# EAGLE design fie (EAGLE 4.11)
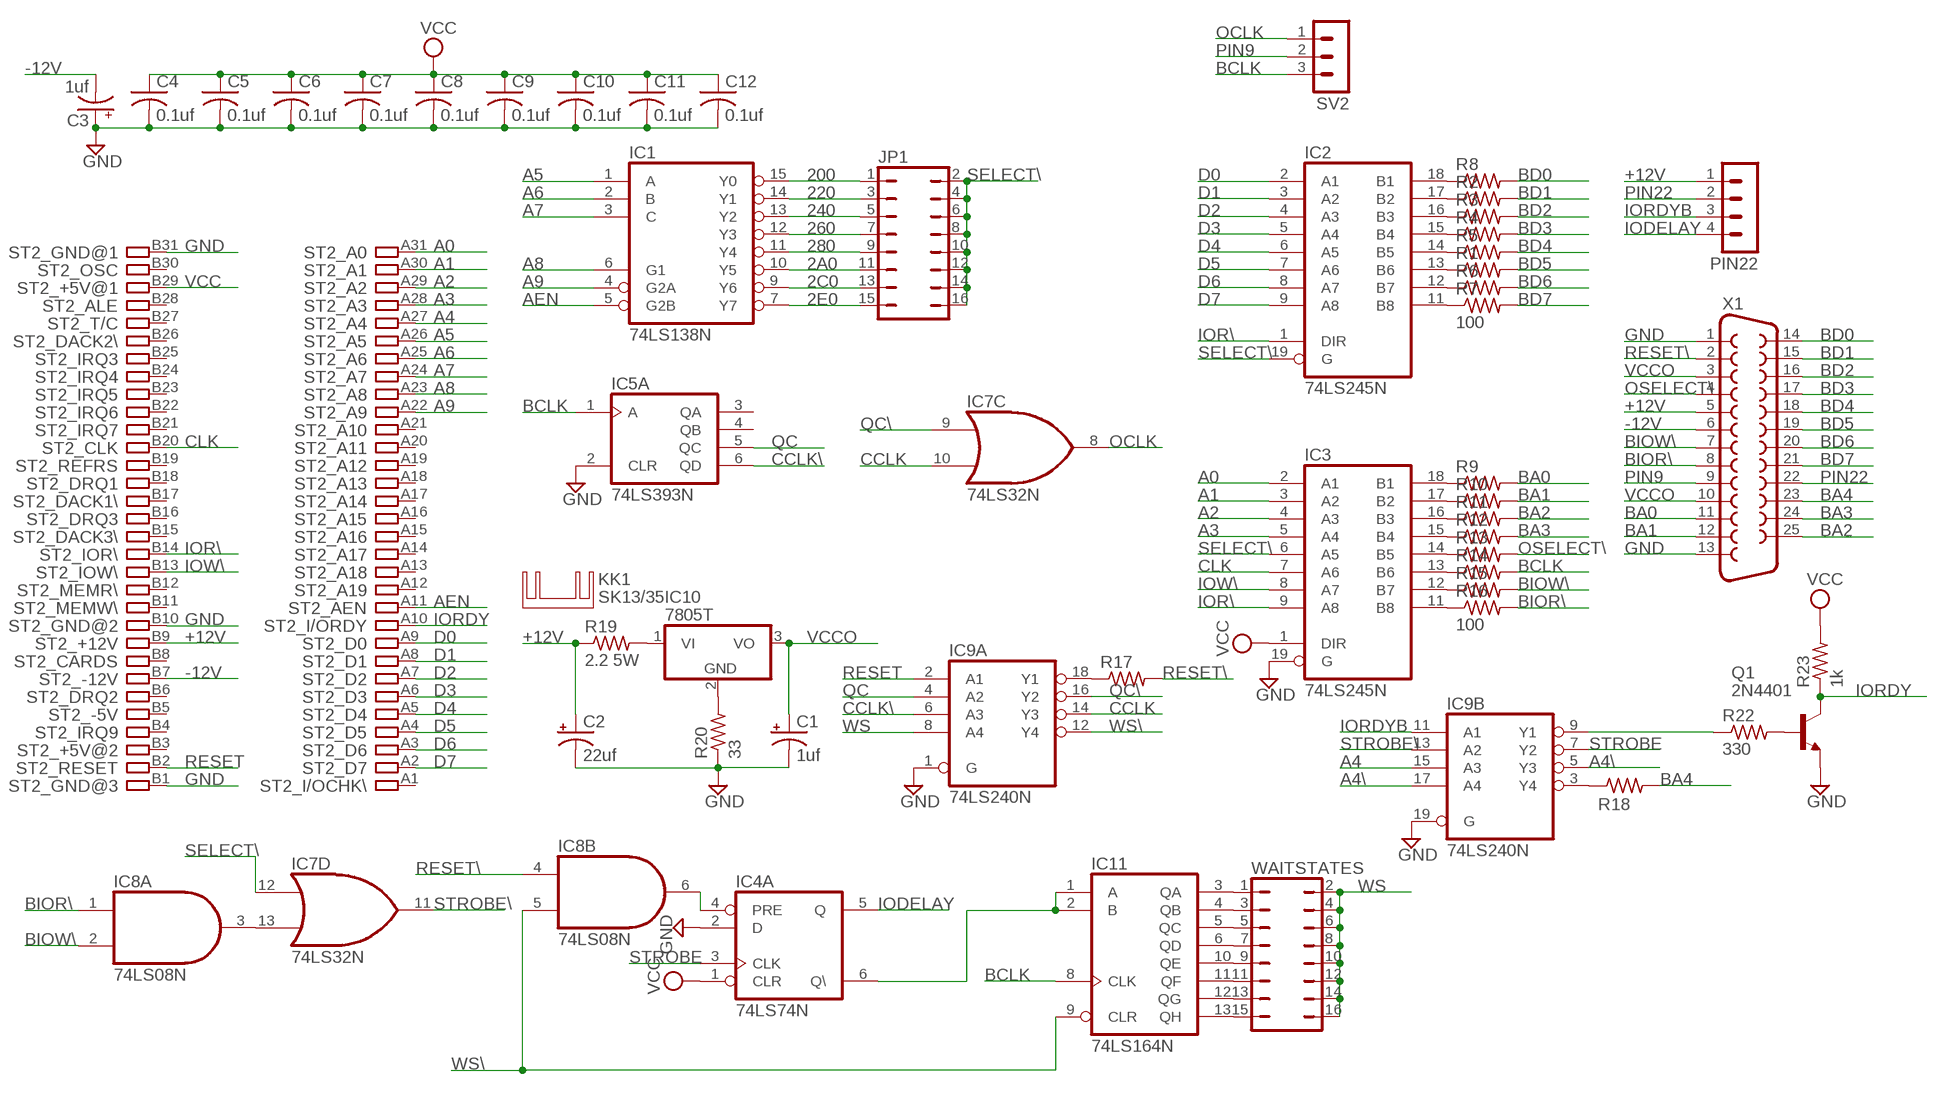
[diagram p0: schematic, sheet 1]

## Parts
C1  1uf  CPOL-USE5-10.5  [E5-10,5]
C2  22uf  CPOL-USE5-10.5  [E5-10,5]
C3  1uf  CPOL-USE5-10.5  [E5-10,5]
C4  0.1uf  C-US050-025X075  [C050-025X075]
C5  0.1uf  C-US050-025X075  [C050-025X075]
C6  0.1uf  C-US050-025X075  [C050-025X075]
C7  0.1uf  C-US050-025X075  [C050-025X075]
C8  0.1uf  C-US050-025X075  [C050-025X075]
C9  0.1uf  C-US050-025X075  [C050-025X075]
C10  0.1uf  C-US050-025X075  [C050-025X075]
C11  0.1uf  C-US050-025X075  [C050-025X075]
C12  0.1uf  C-US050-025X075  [C050-025X075]
IC1  74LS138N  [DIL16]
IC2  74LS245N  [DIL20]
IC3  74LS245N  [DIL20]
IC4  74LS74N  [DIL14]
IC5  74LS393N  [DIL14]
IC7  74LS32N  [DIL14]
IC8  74LS08N  [DIL14]
IC9  74LS240N  [DIL20]
IC10  7805T  [TO220H]
IC11  74LS164N  [DIL14]
JP1  JP8Q  [JP8Q]
KK1  SK13/35  [SK13/35]
PIN22  MA04-1  [MA04-1]
Q1  2N4401  2N4416  [TO92]
R1  R-US_0207/10  [0207/10]
R2  R-US_0207/10  [0207/10]
R3  R-US_0207/10  [0207/10]
R4  R-US_0207/10  [0207/10]
R5  R-US_0207/10  [0207/10]
R6  R-US_0207/10  [0207/10]
R7  100  R-US_0207/10  [0207/10]
R8  R-US_0207/10  [0207/10]
R9  R-US_0207/10  [0207/10]
R10  R-US_0207/10  [0207/10]
R11  R-US_0207/10  [0207/10]
R12  R-US_0207/10  [0207/10]
R13  R-US_0207/10  [0207/10]
R14  R-US_0207/10  [0207/10]
R15  R-US_0207/10  [0207/10]
R16  100  R-US_0207/10  [0207/10]
R17  R-US_0207/10  [0207/10]
R18  R-US_0207/10  [0207/10]
R19  2.2 5W  R-US_0922/22  [0922/22]
R20  33  R-US_0207/10  [0207/10]
R22  330  R-US_0207/10  [0207/10]
R23  1k  R-US_0207/10  [0207/10]
ST2  IBM8BIT  [IBM8BIT]
SV2  MA03-1  [MA03-1]
WAITSTATES  JP8Q  [JP8Q]
X1  F25H  [F25H]

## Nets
2A0: IC1.10(Y5) JP1.11
2C0: IC1.9(Y6) JP1.13
2E0: IC1.7(Y7) JP1.15
200: IC1.15(Y0) JP1.1
220: IC1.14(Y1) JP1.3
240: IC1.13(Y2) JP1.5
260: IC1.12(Y3) JP1.7
280: IC1.11(Y4) JP1.9
+12V [Power]: C2.+ PIN22.1 R19.1 ST2.B9 X1.5
-12V [Power]: C3.- ST2.B7 X1.6
A0: IC3.2(A1) ST2.A31
A1: IC3.3(A2) ST2.A30
A2: IC3.4(A3) ST2.A29
A3: IC3.5(A4) ST2.A28
A4: IC9.15(B:A3) ST2.A27
A4\: IC9.5(B:Y3) IC9.17(B:A4)
A5: IC1.1(A) ST2.A26
A6: IC1.2(B) ST2.A25
A7: IC1.3(C) ST2.A24
A8: IC1.6(G1) ST2.A23
A9: IC1.4(G2A) ST2.A22
AEN: IC1.5(G2B) ST2.A11
BA0: R9.2 X1.11
BA1: R10.2 X1.12
BA2: R11.2 X1.25
BA3: R12.2 X1.24
BA4: R18.2 X1.23
BCLK: IC5.1(A:A) IC11.8(CLK) R14.2 SV2.3
BD0: R8.2 X1.14
BD1: R2.2 X1.15
BD2: R3.2 X1.16
BD3: R4.2 X1.17
BD4: R5.2 X1.18
BD5: R1.2 X1.19
BD6: R6.2 X1.20
BD7: R7.2 X1.21
BIOR\: IC8.1(A:I0) R16.2 X1.8
BIOW\: IC8.2(A:I1) R15.2 X1.7
CCLK: IC7.10(C:I1) IC9.14(A:Y3)
CCLK\: IC5.6(A:QD) IC9.6(A:A3)
CLK: IC3.7(A6) ST2.B20
D0: IC2.2(A1) ST2.A9
D1: IC2.3(A2) ST2.A8
D2: IC2.4(A3) ST2.A7
D3: IC2.5(A4) ST2.A6
D4: IC2.6(A5) ST2.A5
D5: IC2.7(A6) ST2.A4
D6: IC2.8(A7) ST2.A3
D7: IC2.9(A8) ST2.A2
GND [Power]: C1.- C2.- C3.+ C4.2 C5.2 C6.2 C7.2 C8.2 C9.2 C10.2 C11.2 C12.2 IC3.19(G) IC4.2(A:D) IC5.2(A:CLR) IC9.1(A:G) IC9.19(B:G) Q1.3(E) R20.1 ST2.B1 ST2.B10 ST2.B31 X1.1 X1.13
IODELAY: IC4.5(A:Q) PIN22.4
IOR\: IC2.1(DIR) IC3.9(A8) ST2.B14
IORDY: Q1.1(C) R23.1 ST2.A10
IORDYB: IC9.11(B:A1) PIN22.3
IOW\: IC3.8(A7) ST2.B13
N$2 [Power]: IC10.2(GND) R20.2
N$3: IC2.13(B6) R1.1
N$4: IC2.17(B2) R2.1
N$5: IC2.16(B3) R3.1
N$6: IC2.15(B4) R4.1
N$7: IC2.14(B5) R5.1
N$8: IC2.12(B7) R6.1
N$9: IC2.11(B8) R7.1
N$10: IC2.18(B1) R8.1
N$11: IC3.18(B1) R9.1
N$12: IC3.17(B2) R10.1
N$13: IC3.16(B3) R11.1
N$14: IC3.15(B4) R12.1
N$15: IC3.14(B5) R13.1
N$16: IC3.13(B6) R14.1
N$17: IC3.12(B7) R15.1
N$18: IC3.11(B8) R16.1
N$19: IC9.18(A:Y1) R17.1
N$20: IC11.3(QA) WAITSTATES.1
N$21: IC11.4(QB) WAITSTATES.3
N$23: IC9.3(B:Y4) R18.1
N$25 [Power]: IC10.1(VI) R19.2
N$27: IC11.5(QC) WAITSTATES.5
N$28: IC11.6(QD) WAITSTATES.7
N$29: IC7.13(D:I1) IC8.3(A:O)
N$30: IC4.4(A:PRE) IC8.6(B:O)
N$31: IC11.10(QE) WAITSTATES.9
N$32: IC9.9(B:Y1) R22.1
N$34: IC11.11(QF) WAITSTATES.11
N$35: IC11.12(QG) WAITSTATES.13
N$36: IC11.13(QH) WAITSTATES.15
N$37: Q1.2(B) R22.2
N$39: IC4.6(A:Q\) IC11.1(A) IC11.2(B)
OCLK: IC7.8(C:O) SV2.1
OSELECT\: R13.2 X1.4
PIN9: SV2.2 X1.9
PIN22 [Power]: PIN22.2 X1.22
QC: IC5.5(A:QC) IC9.4(A:A2)
QC\: IC7.9(C:I0) IC9.16(A:Y2)
RESET: IC9.2(A:A1) ST2.B2
RESET\: IC8.4(B:I0) R17.2 X1.2
SELECT\: IC2.19(G) IC3.6(A5) IC7.12(D:I0) JP1.2 JP1.4 JP1.6 JP1.8 JP1.10 JP1.12 JP1.14 JP1.16
STROBE: IC4.3(A:CLK) IC9.7(B:Y2)
STROBE\: IC7.11(D:O) IC9.13(B:A2)
VCC [Power]: C4.1 C5.1 C6.1 C7.1 C8.1 C9.1 C10.1 C11.1 C12.1 IC3.1(DIR) IC4.1(A:CLR) R23.2 ST2.B29
VCCO [Power]: C1.+ IC10.3(VO) X1.3 X1.10
WS: IC9.8(A:A4) WAITSTATES.2 WAITSTATES.4 WAITSTATES.6 WAITSTATES.8 WAITSTATES.10 WAITSTATES.12 WAITSTATES.14 WAITSTATES.16
WS\: IC8.5(B:I1) IC9.12(A:Y4) IC11.9(CLR)
Unconnected: IC4.8(B:Q\) IC4.9(B:Q) IC4.10(B:PRE) IC4.11(B:CLK) IC4.12(B:D) IC4.13(B:CLR) IC5.3(A:QA) IC5.4(A:QB) IC5.8(B:QD) IC5.9(B:QC) IC5.10(B:QB) IC5.11(B:QA) IC5.12(B:CLR) IC5.13(B:A) IC7.1(A:I0) IC7.2(A:I1) IC7.3(A:O) IC7.4(B:I0) IC7.5(B:I1) IC7.6(B:O) IC8.8(C:O) IC8.9(C:I0) IC8.10(C:I1) IC8.11(D:O) IC8.12(D:I0) IC8.13(D:I1) ST2.A1 ST2.A12 ST2.A13 ST2.A14 ST2.A15 ST2.A16 ST2.A17 ST2.A18 ST2.A19 ST2.A20 ST2.A21 ST2.B3 ST2.B4 ST2.B5 ST2.B6 ST2.B8 ST2.B11 ST2.B12 ST2.B15 ST2.B16 ST2.B17 ST2.B18 ST2.B19 ST2.B21 ST2.B22 ST2.B23 ST2.B24 ST2.B25 ST2.B26 ST2.B27 ST2.B28 ST2.B30

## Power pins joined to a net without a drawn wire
GND: IC1.8(GND) IC2.10(GND) IC3.10(GND) IC4.7(P:GND) IC5.7(P:GND) IC7.7(P:GND) IC8.7(P:GND) IC9.10(P:GND) IC11.7(GND)
VCC: IC1.16(VCC) IC2.20(VCC) IC3.20(VCC) IC4.14(P:VCC) IC5.14(P:VCC) IC7.14(P:VCC) IC8.14(P:VCC) IC9.20(P:VCC) IC11.14(VCC)

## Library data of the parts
C1-C3 = rcl:CPOL-US: POLARIZED CAPACITOR, American symbol
C4-C12 = rcl:C-US: CAPACITOR, American symbol
IC1 = 74xx-us:74*138: 3-line to 8-line DECODER/DEMULTIPLEXER
IC2 IC3 = 74xx-us:74*245: Octal BUS TRANSCEIVER, 3-state
IC4 = 74xx-us:74*74: Dual D type positive edge triggered FLIP FLOP, preset and clear
IC5 = 74xx-us:74*393: Dual 4-bit decade and binary COUNTER
IC7 = 74xx-us:74*32: Quad 2-input OR gate
IC8 = 74xx-us:74*08: Quad 2-input AND gate
IC9 = 74xx-us:74*240: Octal BUFFER and LINE DRIVER, 3-state
IC10 = linear:78*: Positive VOLTAGE REGULATOR
IC11 = 74xx-us:74*164: 8-bit parallel out SHIFT REGISTER
JP1 WAITSTATES = jumper:JP8Q: JUMPER
KK1 = heatsink:SK13/35: HEATSINK
PIN22 = con-lstb:MA04-1: PIN HEADER
Q1 = transistor-npn:2N4416: NPN Transistor
R1-R20 R22 R23 = rcl:R-US_: RESISTOR, American symbol
ST2 = con-pc:IBM8BIT: 8-bit CARD IBM/PC-AT
SV2 = con-lstb:MA03-1: PIN HEADER
X1 = con-subd:F25: SUB-D

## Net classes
1 Power: width 0.762 mm, drill 0.254 mm

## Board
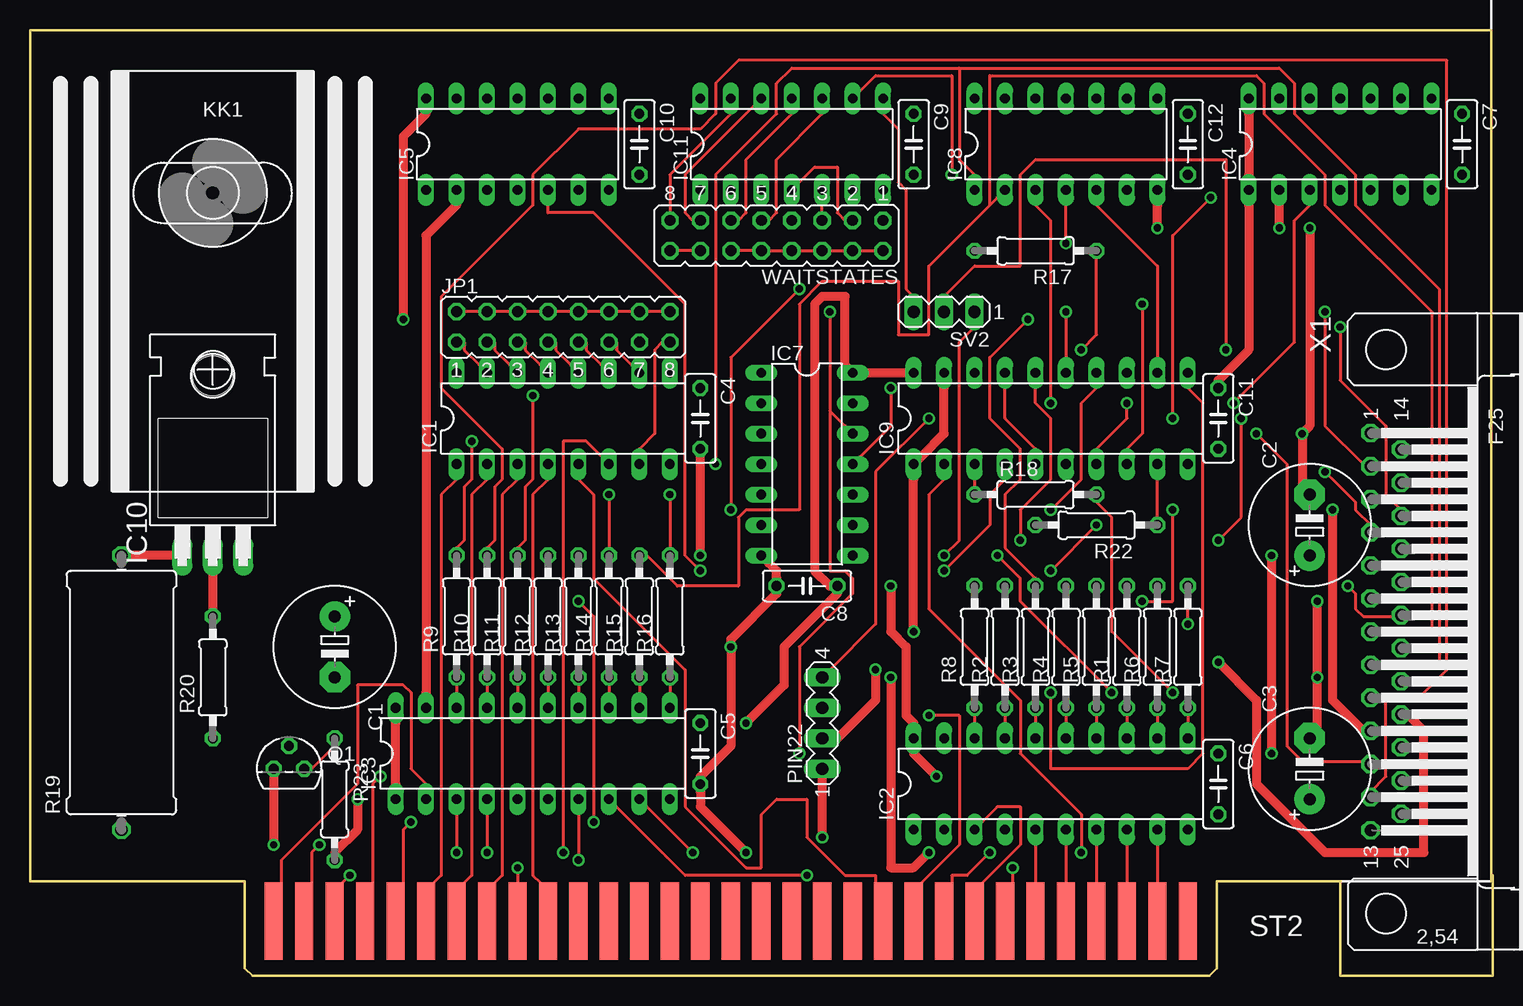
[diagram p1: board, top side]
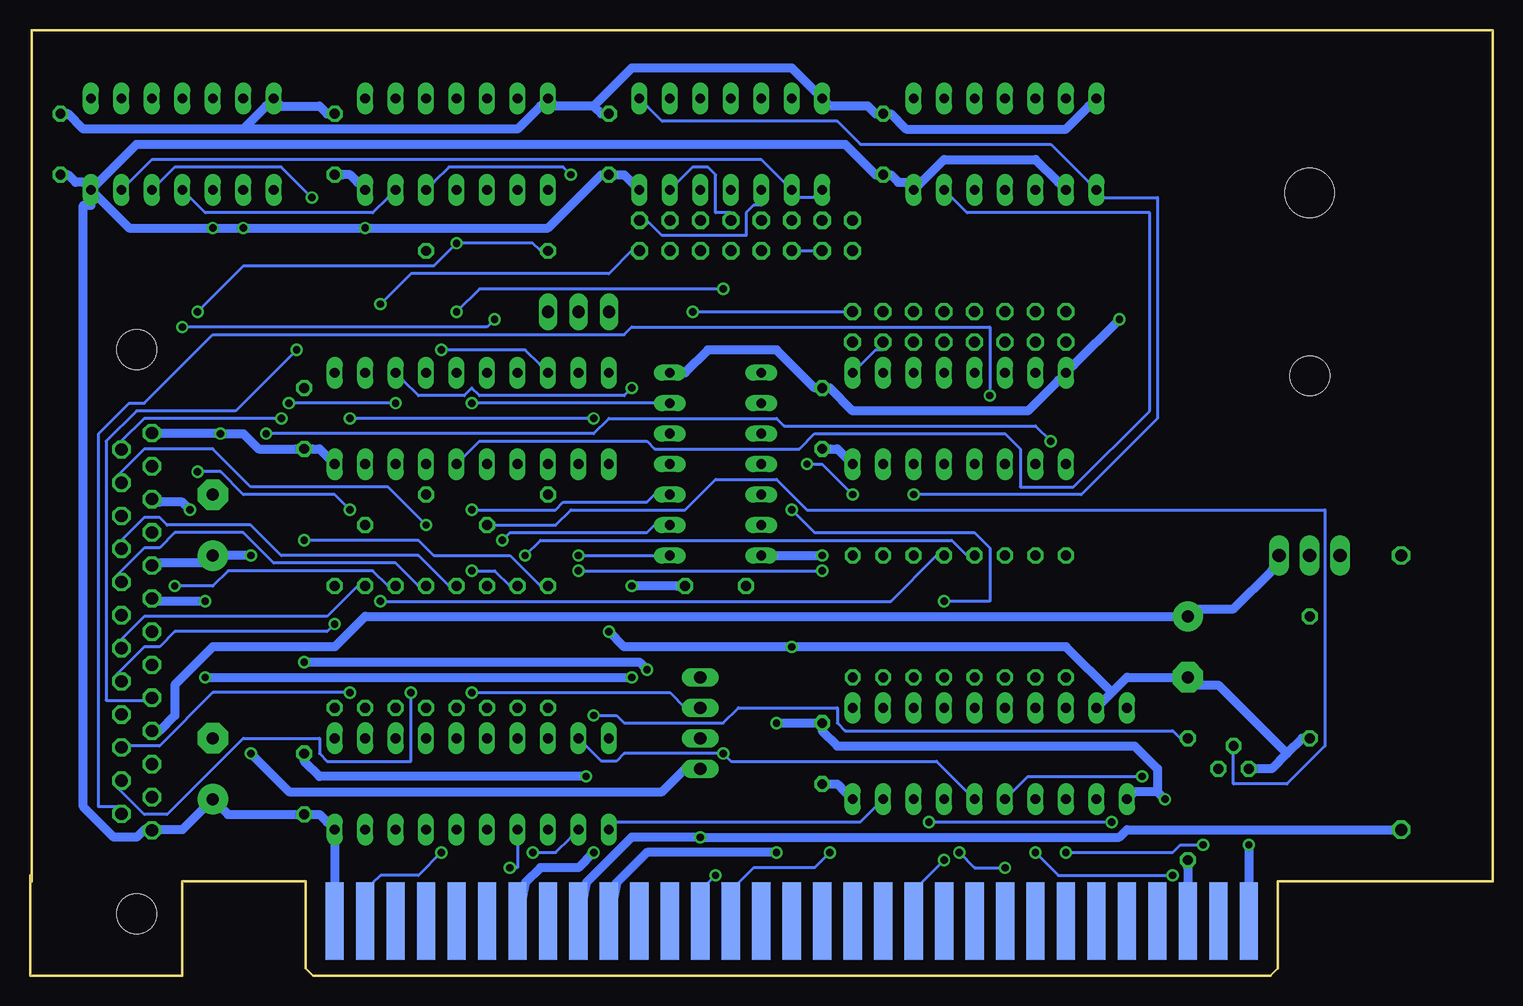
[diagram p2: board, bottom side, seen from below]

Size 121.92 x 78.87 mm. Coordinates in mm from the lower left corner, seen from the top.
Outline: 121.79,7.87 121.79,78.87 0,78.87 0,7.87 17.91,7.87 17.91,0.64 18.54,0 97.79,0 98.3,0 98.93,0.64 98.93,7.87 109.22,7.87 109.22,0 121.92,0 121.92,8.38
Copper layers (1*16): Top 0.035mm / dielectric 1.5mm / Bottom 0.035mm
Design rules "olimex10mil": minimum track width 10mil, minimum drill 24mil, track to track 10mil, track to pad 10mil, pad to pad 10mil, via to via 10mil, smd to smd 10mil, copper to edge 40mil, drill to drill 10mil, minimum pad ring 10mil, minimum via ring 8mil, stop-mask expansion 0mil, vias tented up to drill 0mil, thermal gap 10mil

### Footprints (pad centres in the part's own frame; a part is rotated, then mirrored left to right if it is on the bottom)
E5-10,5 = drill 1.016 pad 2.54 round: + -2.54,0 | drill 1.016 pad 2.54 octagon: - 2.54,0
C050-025X075 = drill 0.813 octagon: 1 -2.54,0; 2 2.54,0
DIL16 = drill 0.813 long: 1 -8.89,-3.81; 2 -6.35,-3.81; 3 -3.81,-3.81; 4 -1.27,-3.81; 5 1.27,-3.81; 6 3.81,-3.81; 7 6.35,-3.81; 8 8.89,-3.81; 9 8.89,3.81; 10 6.35,3.81; 11 3.81,3.81; 12 1.27,3.81; 13 -1.27,3.81; 14 -3.81,3.81; 15 -6.35,3.81; 16 -8.89,3.81
DIL20 = drill 0.813 long: 1 -11.43,-3.81; 2 -8.89,-3.81; 3 -6.35,-3.81; 4 -3.81,-3.81; 5 -1.27,-3.81; 6 1.27,-3.81; 7 3.81,-3.81; 8 6.35,-3.81; 9 8.89,-3.81; 10 11.43,-3.81; 11 11.43,3.81; 12 8.89,3.81; 13 6.35,3.81; 14 3.81,3.81; 15 1.27,3.81; 16 -1.27,3.81; 17 -3.81,3.81; 18 -6.35,3.81; 19 -8.89,3.81; 20 -11.43,3.81
DIL14 = drill 0.813 long: 1 -7.62,-3.81; 2 -5.08,-3.81; 3 -2.54,-3.81; 4 0,-3.81; 5 2.54,-3.81; 6 5.08,-3.81; 7 7.62,-3.81; 8 7.62,3.81; 9 5.08,3.81; 10 2.54,3.81; 11 0,3.81; 12 -2.54,3.81; 13 -5.08,3.81; 14 -7.62,3.81
TO220H = drill 1.118 long: 1 -2.54,-10.16; 2 0,-10.16; 3 2.54,-10.16 | hole 3.302: 0,4.826
JP8Q = drill 0.914 octagon: 1 -8.89,-1.27; 2 -8.89,1.27; 3 -6.35,-1.27; 4 -6.35,1.27; 5 -3.81,-1.27; 6 -3.81,1.27; 7 -1.27,-1.27; 8 -1.27,1.27; 9 1.27,-1.27; 10 1.27,1.27; 11 3.81,-1.27; 12 3.81,1.27; 13 6.35,-1.27; 14 6.35,1.27; 15 8.89,-1.27; 16 8.89,1.27
MA04-1 = drill 1.016 long: 1 -3.81,0; 2 -1.27,0; 3 1.27,0; 4 3.81,0
TO92 = drill 0.813 octagon: 1 1.27,0; 2 0,1.905; 3 -1.27,0
0207/10 = drill 0.813 octagon: 1 -5.08,0; 2 5.08,0
0922/22 = drill 1.016 octagon: 1 -11.43,0; 2 11.43,0
IBM8BIT = smd 1.524 x 6.477: A1 -25.4,5.08; A2 -27.94,5.08; A3 -30.48,5.08; A4 -33.02,5.08; A5 -35.56,5.08; A6 -38.1,5.08; A7 -40.64,5.08; A8 -43.18,5.08; A9 -45.72,5.08; A10 -48.26,5.08; A11 -50.8,5.08; A12 -53.34,5.08; A13 -55.88,5.08; A14 -58.42,5.08; A15 -60.96,5.08; A16 -63.5,5.08; A17 -66.04,5.08; A18 -68.58,5.08; A19 -71.12,5.08; A20 -73.66,5.08; A21 -76.2,5.08; A22 -78.74,5.08; A23 -81.28,5.08; A24 -83.82,5.08; A25 -86.36,5.08; A26 -88.9,5.08; A27 -91.44,5.08; A28 -93.98,5.08; A29 -96.52,5.08; A30 -99.06,5.08; A31 -101.6,5.08 | smd 1.524 x 6.477 bottom: B1 -25.4,5.08; B2 -27.94,5.08; B3 -30.48,5.08; B4 -33.02,5.08; B5 -35.56,5.08; B6 -38.1,5.08; B7 -40.64,5.08; B8 -43.18,5.08; B9 -45.72,5.08; B10 -48.26,5.08; B11 -50.8,5.08; B12 -53.34,5.08; B13 -55.88,5.08; B14 -58.42,5.08; B15 -60.96,5.08; B16 -63.5,5.08; B17 -66.04,5.08; B18 -68.58,5.08; B19 -71.12,5.08; B20 -73.66,5.08; B21 -76.2,5.08; B22 -78.74,5.08; B23 -81.28,5.08; B24 -83.82,5.08; B25 -86.36,5.08; B26 -88.9,5.08; B27 -91.44,5.08; B28 -93.98,5.08; B29 -96.52,5.08; B30 -99.06,5.08; B31 -101.6,5.08
MA03-1 = drill 1.016 long: 1 -2.54,0; 2 0,0; 3 2.54,0
4,1 = hole 4.1: 0,0
F25H = drill 1.016 octagon: 1 -16.561,-1.27; 2 -13.792,-1.27; 3 -11.049,-1.27; 4 -8.28,-1.27; 5 -5.512,-1.27; 6 -2.769,-1.27; 7 0,-1.27; 8 2.769,-1.27; 9 5.512,-1.27; 10 8.28,-1.27; 11 11.049,-1.27; 12 13.792,-1.27; 13 16.561,-1.27; 14 -15.189,1.27; 15 -12.421,1.27; 16 -9.652,1.27; 17 -6.909,1.27; 18 -4.14,1.27; 19 -1.372,1.27; 20 1.372,1.27; 21 4.14,1.27; 22 6.909,1.27; 23 9.652,1.27; 24 12.421,1.27; 25 15.189,1.27 | hole 3.302: -23.52,0; 23.52,0

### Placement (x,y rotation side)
C1  25.4,27.43 270 top
C2  106.68,37.59 90 top
C3  106.68,17.27 90 top
C4  55.88,46.48 270 top
C5  55.88,18.54 270 top
C6  99.06,16 270 top
C7  119.38,69.34 270 top
C8  64.77,32.51 180 top
C9  73.66,69.34 270 top
C10  50.8,69.34 270 top
C11  99.06,46.48 270 top
C12  96.52,69.34 270 top
IC1  44.45,46.48 0 top
IC2  85.09,16 0 top
IC3  41.91,18.54 0 top
IC4  109.22,69.34 0 top
IC5  40.64,69.34 0 top
IC7  64.77,42.67 270 top
IC8  86.36,69.34 0 top
IC9  85.09,46.48 0 top
IC10  15.24,45.21 0 top
IC11  63.5,69.34 0 top
JP1  44.45,54.1 0 top
KK1  15.24,61.72 90 top
PIN22  66.04,21.08 90 top
Q1  21.59,17.27 0 top
R1  91.44,27.43 90 top
R2  81.28,27.43 90 top
R3  83.82,27.43 90 top
R4  86.36,27.43 90 top
R5  88.9,27.43 90 top
R6  93.98,27.43 90 top
R7  96.52,27.43 90 top
R8  78.74,27.43 90 top
R9  35.56,29.97 90 top
R10  38.1,29.97 90 top
R11  40.64,29.97 90 top
R12  43.18,29.97 90 top
R13  45.72,29.97 90 top
R14  48.26,29.97 90 top
R15  50.8,29.97 90 top
R16  53.34,29.97 90 top
R17  83.82,60.45 180 top
R18  83.82,40.13 0 top
R19  7.62,23.62 90 top
R20  15.24,24.89 90 top
R22  88.9,37.59 180 top
R23  25.4,14.73 270 top
ST2  121.92,-0.51 0 top
SV2  76.2,55.37 180 top
U$1  [4,1]  15.24,65.28 0 top
WAITSTATES  62.23,61.72 180 top
X1  113.03,28.7 270 top

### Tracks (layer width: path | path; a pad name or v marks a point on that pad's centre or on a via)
2A0
  Top 0.254: IC1.10 50.17,50.93 48.89,52.2 48.89,52.83 JP1.11
2C0
  Bottom 0.254: IC1.9 52.7,50.93 51.44,52.2 50.8,52.2 JP1.13
2E0
  Top 0.254: IC1.7 50.8,43.94 52.07,45.21 52.07,52.2 52.7,52.83 JP1.15
200
  Top 0.254: IC1.15 37.47,50.93 36.2,52.2 36.2,52.83 JP1.1
220
  Top 0.254: IC1.14 40,50.93 38.73,52.2 38.73,52.83 JP1.3
240
  Top 0.254: IC1.13 42.55,50.93 41.28,52.2 41.28,52.83 JP1.5
260
  Top 0.254: IC1.12 45.09,50.93 43.81,52.2 43.81,52.83 JP1.7
280
  Top 0.254: IC1.11 47.62,50.93 46.36,52.2 46.36,52.83 JP1.9
+12V  (via drill 0.61)
  Top 0.762: v66.04,11.56 66.04,16.64 PIN22.1 | v103.5,18.54 v103.5,35.05
  Bottom 0.762: X1.5 111.12,34.42 107.31,34.42 C2.+ 106.05,35.05 v103.5,35.05 | R19.1 8.25,12.19 30.48,12.19 31.11,11.56 v66.04,11.56 71.75,11.56 75.56,7.75 ST2.B9 | v103.5,18.54 100.33,15.37 69.22,15.37 67.31,17.27 PIN22.1
-12V  (via drill 0.61)
  Top 0.762: v107.31,31.24 v107.31,24.89 107.31,20.45 C3.- | v74.93,10.29 73.66,9.02 71.75,9.02 v71.75,24.89
  Bottom 0.762: v107.31,31.24 111.12,31.24 X1.6 | v74.93,10.29 76.2,9.02 79.38,9.02 80.65,7.75 ST2.B7 | v107.31,24.89 v71.75,24.89
A0
  Top 0.254: IC3.2 33.02,16 31.75,17.27 31.75,23.62 31.11,24.26 27.31,24.26 27.31,16 20.95,9.65 20.95,7.75 ST2.A31
A1  (via drill 0.61)
  Top 0.254: v35.56,10.29 35.56,13.46 IC3.3 | v24.13,10.92 23.5,10.29 23.5,7.75 ST2.A30
  Bottom 0.254: v35.56,10.29 26.67,10.29 26.03,10.92 v24.13,10.92
A2  (via drill 0.61)
  Top 0.254: v38.1,10.29 38.1,13.46 IC3.4 | v26.67,8.38 26.03,7.75 ST2.A29
  Bottom 0.254: v38.1,10.29 36.2,8.38 v26.67,8.38
A3  (via drill 0.61)
  Top 0.254: v29.21,16.64 28.58,16 28.58,7.75 ST2.A28
  Bottom 0.254: v29.21,16.64 38.73,16.64 40,15.37 IC3.5
A4  (via drill 0.61)
  Top 0.254: v86.36,55.37 86.36,51.56 IC9.15 | v64.14,57.28 58.42,51.56 v58.42,38.86 | v45.72,31.24 46.99,29.97 v46.99,12.83 | v31.75,12.83 31.11,12.19 31.11,7.75 ST2.A27
  Bottom 0.254: v86.36,55.37 84.45,57.28 v64.14,57.28 | v58.42,38.86 56.52,36.96 43.18,36.96 41.91,35.69 41.91,31.24 v45.72,31.24 | v46.99,12.83 v31.75,12.83
A4\
  Top 0.254: IC9.5 83.82,43.94 81.28,46.48 81.28,49.02 IC9.17
A5
  Top 0.254: IC1.1 35.56,41.4 34.29,40.13 34.29,8.38 33.66,7.75 ST2.A26
A6
  Top 0.254: IC1.2 38.1,41.4 36.83,40.13 36.83,8.38 36.2,7.75 ST2.A25
A7
  Top 0.254: IC1.3 40.64,41.4 39.37,40.13 39.37,8.38 38.73,7.75 ST2.A24
A8  (via drill 0.61)
  Top 0.254: v44.45,10.29 44.45,44.58 46.36,44.58 47.62,43.31 IC1.6 | v40.64,9.02 40.64,7.75 ST2.A23
  Bottom 0.254: v44.45,10.29 43.18,9.02 v40.64,9.02
A9
  Top 0.254: IC1.4 43.18,41.4 41.91,40.13 41.91,8.38 42.55,7.75 ST2.A22
AEN
  Top 0.254: IC1.5 45.72,41.4 46.99,40.13 46.99,33.15 54.61,25.53 54.61,14.1 59.69,9.02 60.96,9.02 60.96,13.46 62.23,14.73 64.77,14.73 64.77,11.56 67.94,8.38 70.48,8.38 70.48,7.75 ST2.A11
BA0  (via drill 0.61)
  Top 0.254: v36.83,44.58 36.83,41.4 36.2,40.77 36.2,36.32 35.56,35.69 R9.2 | v102.23,45.21 104.78,42.67 104.78,19.18 106.05,17.91 111.12,17.91 X1.11
  Bottom 0.254: v36.83,44.58 38.1,45.85 59.05,45.85 59.69,46.48 73.66,46.48 74.93,45.21 v102.23,45.21
BA1
  Top 0.254: R10.2 38.1,35.69 38.73,36.32 38.73,40.77 39.37,41.4 39.37,43.94 34.29,49.02 34.29,56.64 41.91,64.26 41.91,66.8 45.72,70.61 55.88,70.61 57.15,71.88 57.15,74.42 59.05,76.33 118.11,76.33 118.11,25.53 115.57,22.99 113.03,22.99 113.03,16.64 111.76,15.37 X1.12
BA2  (via drill 0.61)
  Top 0.254: v41.91,48.39 41.91,41.4 41.28,40.77 41.28,36.32 40.64,35.69 R11.2
  Bottom 0.254: v41.91,48.39 41.91,54.1 71.75,54.1 72.39,53.47 106.68,53.47 112.39,47.75 113.67,47.75 116.2,45.21 116.2,14.1 114.3,14.1 X1.25
BA3  (via drill 0.61)
  Top 0.254: v80.65,35.05 82.55,33.15 82.55,31.24 v90.17,23.62
  Bottom 0.254: v80.65,35.05 79.38,36.32 45.09,36.32 43.81,35.05 R12.2 | v90.17,23.62 90.17,17.91 97.16,17.91 97.79,18.54 97.79,19.81 104.14,19.81 110.49,13.46 112.39,13.46 114.94,16 X1.24
BA4  (via drill 0.61)
  Top 0.254: v95.25,23.62 90.17,28.7 90.17,38.23 88.9,39.5 R18.2
  Bottom 0.254: v95.25,23.62 106.68,23.62 111.12,19.18 113.67,19.18 X1.23
BCLK  (via drill 0.61)
  Top 0.254: v48.26,40.13 48.26,35.69 R14.2 | SV2.3 73.66,56.64 73.03,57.28 73.03,65.53 72.39,66.17 72.39,70.61 71.12,71.88 IC11.8
  Bottom 0.254: IC11.8 70.48,72.52 69.22,71.25 54.61,71.25 52.7,69.34 36.83,69.34 33.66,66.17 IC5.1 32.39,64.9 27.94,64.9 27.94,46.48 34.29,40.13 v48.26,40.13
BD0  (via drill 0.61)
  Top 0.254: v99.06,36.32 100.97,38.23 v100.97,46.48
  Bottom 0.254: v99.06,36.32 89.53,36.32 88.27,35.05 81.91,35.05 79.38,32.51 R8.2 | v100.97,46.48 112.39,46.48 114.3,44.58 X1.14
BD1  (via drill 0.61)
  Top 0.254: v85.09,33.78 v88.9,37.59
  Bottom 0.254: v85.09,33.78 83.19,33.78 81.91,32.51 R2.2 | v88.9,37.59 92.08,40.77 103.5,40.77 106.68,43.94 112.39,43.94 114.94,41.4 X1.15
BD2  (via drill 0.61)
  Top 0.254: v83.19,54.74 80.01,51.56 80.01,46.48 82.55,43.94 82.55,41.4 81.28,40.13 81.28,35.69 83.82,33.15 R3.2 | v109.22,54.1 109.22,49.66 113.03,45.85 113.03,40.13 114.3,38.86 X1.16
  Bottom 0.254: v83.19,54.74 83.82,54.1 v109.22,54.1
BD3
  Bottom 0.254: R4.2 87,32.51 89.53,35.05 100.97,35.05 103.5,37.59 110.49,37.59 111.12,38.23 112.39,38.23 114.3,36.32 X1.17
BD4
  Bottom 0.254: R5.2 89.53,32.51 91.44,34.42 101.6,34.42 104.14,36.96 109.86,36.96 111.12,35.69 112.39,35.69 114.94,33.15 X1.18
BD5  (via drill 0.61)
  Top 0.254: v109.86,32.51 110.49,31.88 110.49,30.61 111.12,29.97 113.67,29.97 X1.19
  Bottom 0.254: v109.86,32.51 106.68,32.51 105.41,33.78 93.34,33.78 92.08,32.51 R1.2
BD6
  Bottom 0.254: R6.2 94.62,32.51 97.16,29.97 112.39,29.97 114.3,28.07 X1.20
BD7  (via drill 0.61)
  Top 0.254: v96.52,29.34 96.52,31.88 R7.2
  Bottom 0.254: v96.52,29.34 97.16,28.7 109.86,28.7 111.12,27.43 112.39,27.43 114.94,24.89 X1.21
BIOR\  (via drill 0.61)
  Top 0.254: v53.34,40.13 53.34,35.69 R16.2 | v57.15,42.67 57.15,66.8 62.23,71.88 62.23,74.42 63.5,75.69 77.47,75.69 | 77.47,75.69 77.47,68.07 78.74,66.8 IC8.1 | 77.47,75.69 104.14,75.69 105.41,74.42 105.41,71.88 110.49,66.8 110.49,64.26 117.47,57.28 117.47,26.16 112.39,26.16 X1.8
  Bottom 0.254: v53.34,40.13 55.88,42.67 v57.15,42.67
BIOW\
  Top 0.254: 80.01,64.26 80.65,64.9 IC8.2 | 80.01,64.26 74.93,59.18 74.93,53.47 72.39,53.47 72.39,57.91 66.04,57.91 64.14,56.01 64.14,38.86 59.69,38.86 59.05,38.23 59.05,32.51 53.98,32.51 51.44,35.05 R15.2 | 80.01,64.26 80.01,75.06 102.23,75.06 102.87,74.42 102.87,71.88 107.95,66.8 107.95,64.26 116.84,55.37 116.84,28.7 112.39,28.7 X1.7
CCLK  (via drill 0.61)
  Top 0.254: v85.09,38.86 87.63,41.4 87.63,47.75 88.9,49.02 IC9.14
  Bottom 0.254: v85.09,38.86 78.11,38.86 77.47,39.5 70.48,39.5 69.85,40.13 IC7.10
CCLK\
  Bottom 0.254: IC9.6 85.72,43.31 84.45,44.58 70.48,44.58 69.85,43.94 57.78,43.94 56.52,45.21 40.64,45.21 39.37,43.94 39.37,40.77 34.92,40.77 28.58,47.12 28.58,63.63 43.81,63.63 45.09,64.9 IC5.6
CLK  (via drill 0.61)
  Top 0.254: v45.72,9.65 45.72,13.46 IC3.7
  Bottom 0.254: v45.72,9.65 47.62,7.75 ST2.B20
D0  (via drill 0.61)
  Top 0.254: v80.01,10.29 78.11,8.38 76.84,8.38 76.84,7.75 ST2.A9
  Bottom 0.254: v80.01,10.29 78.11,10.29 76.84,11.56 IC2.2
D1
  Top 0.254: IC2.3 79.38,12.83 80.65,14.1 82.55,14.1 82.55,10.92 79.38,7.75 ST2.A8
D2  (via drill 0.61)
  Top 0.254: v81.91,9.02 81.91,7.75 ST2.A7
  Bottom 0.254: v81.91,9.02 81.28,9.02 81.28,10.92 IC2.4
D3
  Top 0.254: IC2.5 83.82,10.92 83.82,7.75 ST2.A6
D4
  Top 0.254: IC2.6 86.36,10.92 86.36,7.75 ST2.A5
D5
  Top 0.254: IC2.7 88.9,10.92 88.9,7.75 ST2.A4
D6
  Top 0.254: IC2.8 91.44,10.92 91.44,7.75 ST2.A3
D7
  Top 0.254: IC2.9 93.98,10.92 93.98,7.75 ST2.A2
GND  (via drill 0.61)
  Top 0.762: C2.- 106.05,40.77 v106.05,45.21 106.68,45.85 v106.68,62.36 | v104.14,62.36 104.14,64.26 IC4.2 | v93.98,62.36 93.98,64.26 IC8.7 | IC7.7 61.59,34.42 62.23,33.78 62.23,33.15 C8.2 62.23,31.88 58.42,28.07 v58.42,27.43 58.42,19.18 55.88,16.64 C5.2 55.88,15.37 55.88,14.1 v59.69,10.29 | v55.88,35.05 55.88,43.31 C4.2 | IC9.19 76.2,49.02 76.2,45.21 74.3,43.31 IC9.1 73.66,41.4 v73.66,28.7 | v20.32,10.92 20.32,16.64 Q1.3 | IC5.2 35.56,64.26 33.02,61.72 33.02,23.62 IC3.19
  Bottom 0.762: ST2.B1 96.52,7.75 96.52,10.92 IC2.10 97.16,12.83 97.79,13.46 98.42,13.46 C6.2 99.69,13.46 105.41,13.46 106.05,14.1 C3.+ 107.31,14.1 109.22,12.19 111.12,12.19 X1.13 112.39,12.19 113.03,11.56 114.94,11.56 117.47,14.1 117.47,64.26 116.84,64.26 IC4.7 | IC9.10 97.16,43.31 97.79,43.94 98.42,43.94 C11.2 99.69,43.94 102.87,43.94 104.14,45.21 v106.05,45.21 111.12,45.21 X1.1 | IC8.7 94.62,66.17 95.25,66.8 95.89,66.8 C12.2 | IC11.7 71.75,66.17 72.39,66.8 73.03,66.8 C9.2 74.3,66.8 78.74,62.36 v93.98,62.36 v104.14,62.36 v106.68,62.36 113.67,62.36 116.2,64.9 IC4.7 | C7.2 118.75,66.8 118.11,66.17 117.47,66.17 IC4.7 | IC1.8 53.98,43.31 54.61,43.94 55.25,43.94 C4.2 | IC3.10 53.98,15.37 54.61,16 55.25,16 C5.2 | v55.88,35.05 59.69,35.05 IC7.7 | v59.69,10.29 70.48,10.29 73.03,7.75 ST2.B10 | IC5.2 36.2,66.17 38.1,68.07 45.72,68.07 47.62,66.17 IC5.7 48.89,66.17 49.53,66.17 50.17,66.8 C10.2 51.44,66.8 53.98,69.34 113.03,69.34 116.2,66.17 IC4.7 | 17.14,18.54 18.42,17.27 19.69,17.27 Q1.3 | 17.14,18.54 15.88,19.81 R20.1 | 31.75,23.62 30.48,24.89 26.03,24.89 C1.- 24.77,24.26 22.86,24.26 17.14,18.54 | 31.75,23.62 32.39,22.99 IC3.19 | v73.66,28.7 72.39,27.43 v58.42,27.43 35.56,27.43 31.75,23.62 | v20.32,10.92 20.32,7.75 ST2.B31
IODELAY  (via drill 0.61)
  Top 0.254: v98.42,64.9 95.25,61.72 v95.25,46.48 | v74.93,46.48 70.48,42.04 70.48,29.34 66.68,25.53 PIN22.4
  Bottom 0.254: v98.42,64.9 100.97,67.44 109.86,67.44 111.12,66.17 IC4.5 | v74.93,46.48 v95.25,46.48
IOR\  (via drill 0.61)
  Top 0.254: v55.25,10.29 51.44,14.1 IC3.9
  Bottom 0.254: IC2.1 73.03,12.83 52.7,12.83 51.44,14.1 IC3.9 | v55.25,10.29 56.52,9.02 61.59,9.02 62.87,7.75 ST2.B14
IORDY  (via drill 0.61)
  Top 0.254: Q1.1 23.5,17.27 25.4,19.18 R23.1 | v74.93,21.72 77.47,21.72 77.47,10.92 74.3,7.75 ST2.A10
  Bottom 0.254: v74.93,21.72 73.03,21.72 72.39,21.08 64.14,21.08 62.87,22.35 54.61,22.35 54.61,21.08 53.98,20.45 26.67,20.45 26.03,19.81 R23.1
IORDYB  (via drill 0.61)
  Top 0.254: v85.09,23.62 85.09,17.27 96.52,17.27 97.79,18.54 97.79,47.75 96.52,49.02 IC9.11
  Bottom 0.254: v85.09,23.62 68.58,23.62 67.31,22.35 PIN22.3
IOW\  (via drill 0.61)
  Top 0.254: v64.77,8.38 54.61,8.38 48.89,14.1 IC3.8
  Bottom 0.254: v64.77,8.38 65.41,7.75 ST2.B13
N$2
  Top 0.762: R20.2 15.24,30.61 15.24,33.78 IC10.2
N$3
  Top 0.254: IC2.13 91.44,21.08 91.44,21.72 R1.1
N$4
  Top 0.254: IC2.17 81.28,21.08 81.28,21.72 R2.1
N$5
  Top 0.254: IC2.16 83.82,21.08 83.82,21.72 R3.1
N$6
  Top 0.254: IC2.15 86.36,21.08 86.36,21.72 R4.1
N$7
  Top 0.254: IC2.14 88.9,21.08 88.9,21.72 R5.1
N$8
  Top 0.254: IC2.12 93.98,21.08 93.98,21.72 R6.1
N$9
  Top 0.254: IC2.11 96.52,21.08 96.52,21.72 R7.1
N$10
  Top 0.254: IC2.18 78.74,21.08 78.74,21.72 R8.1
N$11
  Top 0.254: IC3.18 35.56,23.62 35.56,24.26 R9.1
N$12
  Top 0.254: IC3.17 38.1,23.62 38.1,24.26 R10.1
N$13
  Top 0.254: IC3.16 40.64,23.62 40.64,24.26 R11.1
N$14
  Top 0.254: IC3.15 43.18,23.62 43.18,24.26 R12.1
N$15
  Top 0.254: IC3.14 45.72,23.62 45.72,24.26 R13.1
N$16
  Top 0.254: IC3.13 48.26,23.62 48.26,24.26 R14.1
N$17
  Top 0.254: IC3.12 50.8,23.62 50.8,24.26 R15.1
N$18
  Top 0.254: IC3.11 53.34,23.62 53.34,24.26 R16.1
N$19  (via drill 0.61)
  Top 0.254: v87.63,52.2 88.9,53.47 88.9,59.82 R17.1
  Bottom 0.254: v87.63,52.2 80.65,52.2 79.38,50.93 IC9.18
N$20
  Bottom 0.254: IC11.3 60.96,64.26 61.59,64.26 62.23,63.63 62.23,61.72 69.22,61.72 70.48,62.99 WAITSTATES.1
N$21
  Top 0.254: IC11.4 64.14,66.17 65.41,67.44 67.31,67.44 67.31,63.63 67.94,62.99 WAITSTATES.3
N$23
  Top 0.254: R18.1 78.74,40.77 78.74,41.4 IC9.3
N$25
  Top 0.762: R19.2 8.25,35.05 12.06,35.05 IC10.1
N$27
  Top 0.254: IC11.5 66.04,64.26 66.04,63.63 WAITSTATES.5
N$28
  Bottom 0.254: IC11.6 67.94,66.17 66.68,67.44 65.41,67.44 64.77,66.8 64.77,63.63 63.5,63.63 WAITSTATES.7
N$29  (via drill 0.61)
  Top 0.254: v85.09,47.75 85.09,62.99 83.82,64.26 IC8.3
  Bottom 0.254: v85.09,47.75 69.85,47.75 IC7.13
N$30
  Bottom 0.254: IC8.6 92.08,64.9 93.34,63.63 107.31,63.63 108.59,64.9 IC4.4
N$31
  Top 0.254: IC11.10 66.04,71.88 62.23,68.07 62.23,63.63 61.59,62.99 WAITSTATES.9
N$32
  Top 0.254: R22.1 93.98,38.23 93.98,41.4 IC9.9
N$34
  Top 0.254: IC11.11 63.5,71.88 59.69,68.07 59.69,63.63 59.05,62.99 WAITSTATES.11
N$35
  Top 0.254: IC11.12 60.33,72.52 54.61,66.8 54.61,63.63 55.25,62.99 WAITSTATES.13
N$36
  Top 0.254: IC11.13 58.42,71.88 53.34,66.8 53.34,63.63 WAITSTATES.15
N$37
  Bottom 0.254: Q1.2 21.59,18.54 21.59,16 17.14,16 13.97,19.18 13.97,38.86 57.15,38.86 59.69,41.4 64.77,41.4 67.31,38.86 76.84,38.86 78.11,37.59 83.19,37.59 R22.2
N$39
  Bottom 0.254: IC11.1 56.52,64.9 57.78,64.9 IC11.2 59.05,66.17 60.96,68.07 111.76,68.07 113.67,66.17 IC4.6
OCLK  (via drill 0.61)
  Top 0.254: v76.2,35.05 77.47,36.32 77.47,52.83 78.74,54.1 SV2.1
  Bottom 0.254: v76.2,35.05 69.85,35.05 IC7.8
OSELECT\  (via drill 0.61)
  Top 0.254: v92.71,31.24 95.25,31.24 v95.25,38.86 | v107.95,42.04 110.49,39.5 110.49,38.86 111.76,37.59 X1.4
  Bottom 0.254: v92.71,31.24 50.17,31.24 46.36,35.05 R13.2 | v95.25,38.86 96.52,40.13 104.14,40.13 106.05,42.04 v107.95,42.04
PIN9  (via drill 0.61)
  Top 0.254: v99.69,52.2 99.69,68.07 83.82,68.07 82.55,66.8 82.55,59.18 78.74,59.18 76.2,56.64 SV2.2
  Bottom 0.254: v99.69,52.2 104.78,47.12 113.03,47.12 115.57,44.58 115.57,22.99 112.39,22.99 X1.9
PIN22  (via drill 0.61)
  Top 0.762: v70.48,25.53 70.48,22.99 67.31,19.81 PIN22.2 | v99.06,26.16 102.23,22.99 102.23,16 107.95,10.29 116.2,10.29 116.2,20.45 114.94,21.72 X1.22
  Bottom 0.762: v70.48,25.53 71.12,26.16 v99.06,26.16
QC  (via drill 0.61)
  Top 0.254: v76.2,33.78 80.01,37.59 80.01,40.13 81.28,41.4 IC9.4 | v55.88,33.78 54.61,35.05 54.61,56.01 46.99,63.63 43.18,63.63 43.18,64.26 IC5.5
  Bottom 0.254: v76.2,33.78 v55.88,33.78
QC\  (via drill 0.61)
  Top 0.254: v82.55,36.32 82.55,38.86 85.09,41.4 85.09,46.48 83.82,47.75 83.82,49.02 IC9.16
  Bottom 0.254: v82.55,36.32 81.91,36.96 70.48,36.96 69.85,37.59 IC7.9
RESET  (via drill 0.61)
  Top 0.254: v87.63,10.29 87.63,13.46 82.55,18.54 82.55,22.99 74.93,30.61 74.93,40.13 76.2,41.4 IC9.2
  Bottom 0.254: v87.63,10.29 89.53,8.38 92.71,8.38 93.34,7.75 ST2.B2
RESET\  (via drill 0.61)
  Top 0.254: v86.36,61.09 86.36,64.26 IC8.4 | v107.95,55.37 107.95,45.85 111.12,42.67 X1.2
  Bottom 0.254: R17.2 79.38,60.45 80.01,61.09 v86.36,61.09 88.27,59.18 104.14,59.18 v107.95,55.37
SELECT\  (via drill 0.61)
  Top 0.254: JP1.2 36.2,55.37 37.47,55.37 JP1.4 38.73,55.37 40,55.37 JP1.6 41.28,55.37 42.55,55.37 JP1.8 43.81,55.37 45.09,55.37 JP1.10 46.36,55.37 47.62,55.37 JP1.12 48.89,55.37 50.17,55.37 JP1.14 51.44,55.37 52.7,55.37 JP1.16 | 66.68,47.12 67.94,45.85 IC7.12 | v66.68,55.37 66.68,47.12 | v64.14,18.54 64.14,27.43 68.58,31.88 68.58,33.15 67.94,33.78 66.68,33.78 66.68,47.12
  Bottom 0.254: IC3.6 43.81,15.37 46.36,17.91 63.5,17.91 v64.14,18.54 72.39,18.54 73.03,17.91 74.3,17.91 75.56,19.18 IC2.19 | v66.68,55.37 53.98,55.37 JP1.16
STROBE  (via drill 0.61)
  Top 0.254: v91.44,47.75 91.44,46.48 88.9,43.94 IC9.7 | v100.33,47.75 105.41,52.83 105.41,62.99 106.68,64.26 IC4.3
  Bottom 0.254: v91.44,47.75 v100.33,47.75
STROBE\  (via drill 0.61)
  Top 0.254: v71.75,49.02 71.75,45.85 69.22,43.31 IC7.11
  Bottom 0.254: v71.75,49.02 72.39,48.39 84.45,48.39 85.09,49.02 85.72,48.39 89.53,48.39 90.81,49.66 IC9.13
VCC  (via drill 0.61)
  Top 0.762: C11.1 99.06,49.66 101.6,52.2 101.6,64.26 IC4.1 101.6,66.8 101.6,71.88 IC4.14 | IC3.1 30.48,16 30.48,21.08 IC3.20 | v27.31,14.73 27.31,12.19 25.4,10.29 R23.2 | v71.75,32.51 71.75,28.7 73.03,27.43 73.03,21.72 73.66,21.08 IC2.20 73.66,18.54 v75.56,16.64 | IC9.20 73.03,50.29 69.85,50.29 IC7.14 67.94,50.93 67.94,56.64 66.04,56.64 65.41,56.01 65.41,33.78 66.68,32.51 C8.1 67.31,31.88 62.87,27.43 62.87,24.26 v59.69,21.08 | v31.11,54.74 31.11,69.98 33.02,71.88 IC5.14
  Bottom 0.762: IC5.14 33.66,72.52 35.56,70.61 48.89,70.61 50.17,71.88 C10.1 51.44,71.88 52.07,72.52 55.25,72.52 IC11.14 56.52,73.79 58.42,75.69 71.75,75.69 74.93,72.52 | 74.93,72.52 74.3,71.88 C9.1 | 74.93,72.52 78.11,72.52 IC8.14 79.38,72.52 81.28,70.61 104.14,70.61 | C12.1 97.16,71.88 97.79,72.52 100.97,72.52 IC4.14 102.23,72.52 104.14,70.61 | 104.14,70.61 117.47,70.61 118.75,71.88 C7.1 | R23.2 25.4,9.02 25.4,7.75 ST2.B29 | 27.94,15.37 27.94,17.27 29.84,19.18 54.61,19.18 55.88,20.45 C5.1 56.52,21.08 v59.69,21.08 | 27.94,15.37 29.84,15.37 IC3.1 | 27.94,15.37 v27.31,14.73 | v71.75,32.51 67.94,32.51 C8.1 | IC7.14 67.31,50.29 65.41,52.2 59.69,52.2 56.52,49.02 C4.1 55.25,49.02 53.34,47.12 38.73,47.12 36.2,49.66 IC1.16 34.92,50.93 v31.11,54.74 | v75.56,16.64 97.79,16.64 99.06,17.91 C6.1
VCCO  (via drill 0.61)
  Top 0.762: v108.59,38.86 108.59,22.99 111.12,20.45 X1.10
  Bottom 0.762: IC10.3 18.42,33.78 21.59,30.61 24.77,30.61 C1.+ 26.03,29.97 93.98,29.97 96.52,27.43 106.68,27.43 109.86,24.26 109.86,21.72 111.12,20.45 X1.10 | v108.59,38.86 109.22,39.5 111.12,39.5 X1.3
WS  (via drill 0.61)
  Top 0.254: WAITSTATES.16 53.98,60.45 55.25,60.45 WAITSTATES.14 | WAITSTATES.12 59.05,60.45 60.33,60.45 WAITSTATES.10 61.59,60.45 62.87,60.45 WAITSTATES.8 64.14,60.45 65.41,60.45 WAITSTATES.6 66.68,60.45 67.94,60.45 WAITSTATES.4 69.22,60.45 70.48,60.45 WAITSTATES.2 | v92.71,56.01 92.71,45.21 91.44,43.94 IC9.8
  Bottom 0.254: WAITSTATES.12 57.78,60.45 56.52,60.45 WAITSTATES.14 | v92.71,56.01 90.17,58.55 73.66,58.55 71.75,60.45 WAITSTATES.2
WS\  (via drill 0.61)
  Top 0.254: v76.84,66.8 76.84,75.06 70.48,75.06 69.22,73.79 IC11.9 | IC9.12 93.98,51.56 93.98,59.18 88.9,64.26 IC8.5
  Bottom 0.254: v76.84,66.8 77.47,67.44 87,67.44 88.27,66.17 IC8.5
